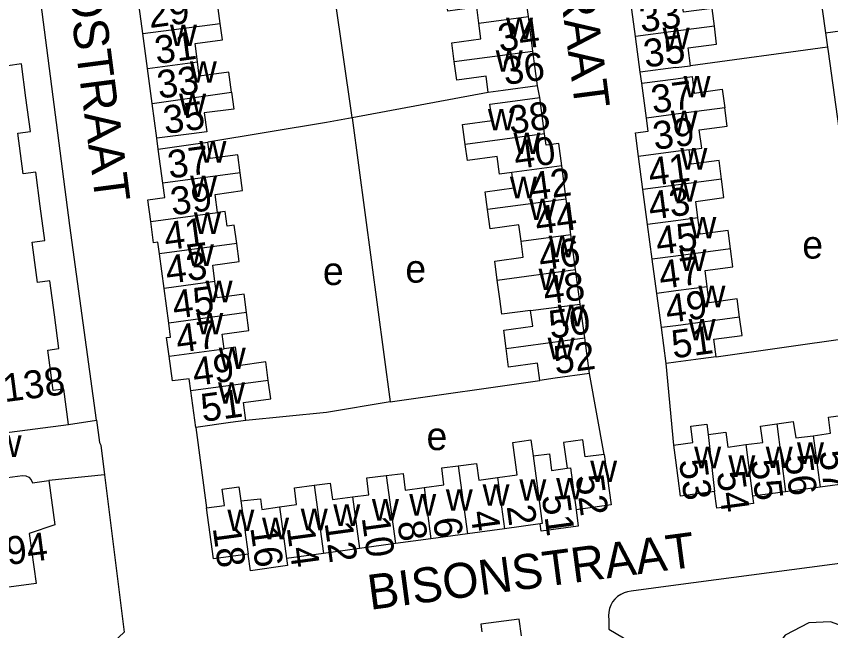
# Model space of a CAD drawing. Extents: x 162667 to 164645, y 379003 to 382150.
# Drawn here: x 163255.6 to 163372.2, y 381289.7 to 381377.6 of the extents above; entities that cross this region are included whole.
import ezdxf

# ---------------------------------------------------------------- set-up
doc = ezdxf.new("R2010")
doc.units = 0
for name, color, linetype in [('BLT_Basislijn', 7, 'Continuous'), ('BLT_Bebouwing', 7, 'Continuous'), ('BLT_Centroide', 7, 'Continuous'), ('BLT_Huisnummer', 7, 'Continuous'), ('BLT_Huisnummer_ tussenligend', 7, 'Continuous'), ('BLT_Huisnummer_reeks', 7, 'Continuous'), ('BLT_Onderverdeling_panden', 7, 'Continuous'), ('BLT_Straatnaam', 7, 'Continuous')]:
    doc.layers.add(name, color=color, linetype=linetype)

msp = doc.modelspace()

# ---------------------------------------------------------------- linework, layer by layer
at = {"layer": 'BLT_Basislijn'}
for p, q in [((163371.46, 381375.22), (163392.43, 381378.07)), ((163371.46, 381375.22), (163371.75, 381373.19)), ((163371.75, 381373.19), (163352.11, 381370.53)), ((163345.14, 381368.03), (163344.89, 381369.59)), ((163323.15, 381366.7), (163303.66, 381363.07)), ((163330.52, 381365.99), (163330.22, 381367.64)), ((163303.66, 381363.07), (163309.12, 381322.44)), ((163275.91, 381358.61), (163275.69, 381360.14)), ((163355.81, 381328.89), (163377.46, 381331.93)), ((163349.71, 381316.26), (163348.62, 381327.93)), ((163339.77, 381314.92), (163337.67, 381326.47)), ((163309.12, 381322.44), (163330.54, 381325.51)), ((163263.08, 381319.2), (163267.07, 381319.8)), ((163281.27, 381318.78), (163282.82, 381307.25)), ((163268.19, 381312), (163260.24, 381311.17)), ((163410.34, 381304.2), (163350, 381296.19)), ((163350, 381296.19), (163343.63, 381295.34))]:
    msp.add_line(p, q, dxfattribs=at)
for points in [[(163267.07, 381319.8), (163263.26, 381347.66), (163252.71, 381428.73)], [(163365.09, 381420.96), (163365.18, 381420.22), (163371.36, 381375.91), (163371.46, 381375.22)], [(163303.66, 381363.07), (163303.61, 381363.44), (163300, 381388.75), (163296.66, 381413.91)], [(163371.75, 381373.19), (163371.85, 381372.54), (163377.46, 381331.93)], [(163303.66, 381363.07), (163300, 381362.38), (163283.03, 381359.58)], [(163309.12, 381322.44), (163300, 381320.93), (163288.45, 381319.76)], [(163267.07, 381319.8), (163267.51, 381316.62), (163267.67, 381316.24), (163268.19, 381312)], [(163268.19, 381312), (163271.01, 381289.49), (163250.88, 381270.62), (163195.97, 381221.79)], [(163343.63, 381295.34), (163343.11, 381295.27), (163342.6, 381295.11), (163342.12, 381294.88), (163341.68, 381294.58), (163341.29, 381294.22), (163340.96, 381293.8), (163340.7, 381293.34), (163340.51, 381292.85), (163340.4, 381292.33), (163340.36, 381291.8), (163340.42, 381291.21)], [(163340.42, 381291.21), (163340.42, 381289.9), (163342.54, 381288.69), (163343.44, 381282.73), (163341.63, 381280.91), (163341.75, 381280.09)], [(163369.93, 381274.98), (163373.68, 381275.4), (163375.87, 381276.61), (163377.82, 381278.8), (163378.87, 381281.62), (163378.76, 381285.42), (163377.01, 381288.26), (163374.95, 381289.95), (163372.15, 381290.94), (163369.04, 381290.81), (163365.68, 381289.03), (163363.81, 381286.6), (163362.99, 381283.68), (163363.3, 381280.68), (163364.6, 381278.13), (163365.12, 381277.66)]]:
    msp.add_lwpolyline(points, dxfattribs=at)
at = {"layer": 'BLT_Bebouwing'}
for p, q in [((163328.9, 381377.57), (163328.25, 381382.52)), ((163273.71, 381375.12), (163273.05, 381380.11)), ((163344.23, 381374.7), (163343.59, 381379.61)), ((163329.56, 381372.63), (163328.9, 381377.57)), ((163274.37, 381370.13), (163273.71, 381375.12)), ((163344.89, 381369.59), (163344.23, 381374.7)), ((163330.22, 381367.64), (163329.56, 381372.63)), ((163275.03, 381365.14), (163274.37, 381370.13)), ((163350, 381370.25), (163344.89, 381369.59)), ((163350, 381370.25), (163352.11, 381370.53)), ((163345.14, 381368.03), (163350, 381368.67)), ((163345.81, 381363.02), (163345.14, 381368.03)), ((163331.22, 381360.78), (163330.52, 381365.99)), ((163275.69, 381360.14), (163275.03, 381365.14)), ((163276.58, 381353.72), (163275.91, 381358.61)), ((163345.31, 381352.82), (163344.69, 381357.52)), ((163334.32, 381351.45), (163333.68, 381356.2)), ((163345.98, 381347.81), (163345.31, 381352.82)), ((163334.99, 381346.4), (163334.32, 381351.45)), ((163346.64, 381342.86), (163345.98, 381347.81)), ((163335.67, 381341.37), (163334.99, 381346.4)), ((163276.74, 381338.66), (163276.07, 381343.61)), ((163347.29, 381337.95), (163346.64, 381342.86)), ((163336.33, 381336.43), (163335.67, 381341.37)), ((163277.41, 381333.71), (163276.74, 381338.66)), ((163347.94, 381333.05), (163347.29, 381337.95)), ((163336.99, 381331.57), (163336.33, 381336.43)), ((163348.62, 381327.93), (163347.94, 381333.05)), ((163337.67, 381326.47), (163336.99, 381331.57)), ((163350, 381328.11), (163348.62, 381327.93)), ((163281.27, 381318.78), (163280.57, 381324)), ((163253.53, 381317.94), (163263.08, 381319.2)), ((163349.71, 381316.26), (163350, 381316.3)), ((163350, 381314.11), (163349.71, 381316.26)), ((163375.61, 381310.9), (163370.66, 381310.24)), ((163365.72, 381309.58), (163361.01, 381308.96)), ((163370.66, 381310.24), (163365.72, 381309.58)), ((163330.58, 381304.97), (163325.48, 381304.28)), ((163325.48, 381304.28), (163320.2, 381303.56)), ((163314.95, 381302.85), (163309.86, 381302.16)), ((163320.2, 381303.56), (163314.95, 381302.85)), ((163309.86, 381302.16), (163304.71, 381301.46)), ((163299.56, 381300.76), (163294.29, 381300.04))]:
    msp.add_line(p, q, dxfattribs=at)
for points in [[(163284.79, 381376.58), (163284.41, 381379.42), (163280.48, 381378.9), (163280.19, 381381.05)], [(163321.81, 381376.62), (163321.51, 381378.9), (163317.36, 381378.35), (163317.01, 381381.02)], [(163355.53, 381376.17), (163355.2, 381378.72), (163351.09, 381378.19), (163350.78, 381380.55)], [(163281.52, 381371.07), (163281.17, 381373.71), (163285.1, 381374.23), (163284.79, 381376.58)], [(163318.29, 381371.14), (163317.94, 381373.8), (163322.11, 381374.36), (163321.81, 381376.62)], [(163352.11, 381370.53), (163351.78, 381373.08), (163355.86, 381373.62), (163355.53, 381376.17)], [(163256.97, 381365.95), (163256.33, 381370.78), (163254.39, 381370.52), (163254, 381373.42)], [(163286.4, 381366.73), (163286.01, 381369.61), (163281.78, 381369.05), (163281.52, 381371.07)], [(163323.15, 381366.7), (163322.84, 381369.03), (163318.65, 381368.47), (163318.29, 381371.14)], [(163350, 381368.67), (163352.34, 381368.98), (163352.65, 381366.62), (163356.67, 381367.16), (163357.02, 381364.51)], [(163286.4, 381366.73), (163286.72, 381364.33), (163282.49, 381363.78), (163282.85, 381361.08), (163280.65, 381360.79), (163275.69, 381360.14)], [(163330.22, 381367.64), (163325.27, 381366.98), (163323.15, 381366.7)], [(163256.19, 381357.98), (163255.81, 381360.88), (163257.61, 381361.12), (163256.97, 381365.95)], [(163319.87, 381359.25), (163319.49, 381362.11), (163323.7, 381362.68), (163323.38, 381365.03), (163325.56, 381365.33), (163330.52, 381365.99)], [(163351.93, 381358.49), (163353.72, 381358.73), (163353.37, 381361.33), (163357.37, 381361.86), (163357.02, 381364.51)], [(163344.69, 381357.52), (163344.24, 381360.9), (163346.06, 381361.14), (163345.81, 381363.02)], [(163333.68, 381356.2), (163333.25, 381359.39), (163331.44, 381359.14), (163331.22, 381360.78)], [(163275.91, 381358.61), (163280.93, 381359.3), (163283.03, 381359.58)], [(163287.62, 381355.22), (163287.28, 381357.78), (163283.35, 381357.25), (163283.03, 381359.58)], [(163326.55, 381355.24), (163324.78, 381355), (163324.44, 381357.53), (163320.18, 381356.96), (163319.87, 381359.25)], [(163356.56, 381354.31), (163356.2, 381356.97), (163352.2, 381356.44), (163351.93, 381358.49)], [(163259.01, 381350.41), (163258.36, 381355.31), (163256.58, 381355.07), (163256.19, 381357.98)], [(163284.39, 381349.53), (163284.04, 381352.11), (163287.97, 381352.65), (163287.62, 381355.22)], [(163323.07, 381349.94), (163322.71, 381352.48), (163326.84, 381353.04), (163326.55, 381355.24)], [(163353.18, 381348.76), (163352.86, 381351.11), (163356.91, 381351.65), (163356.56, 381354.31)], [(163274.83, 381348.23), (163274.4, 381351.35), (163276.85, 381351.68), (163276.58, 381353.72)], [(163258.24, 381342.38), (163257.86, 381345.27), (163259.66, 381345.51), (163259.01, 381350.41)], [(163287.14, 381345.11), (163286.78, 381347.73), (163285.78, 381347.59), (163285.49, 381349.66), (163284.39, 381349.53)], [(163327.87, 381345.44), (163327.56, 381347.75), (163323.43, 381347.2), (163323.07, 381349.94)], [(163276.07, 381343.61), (163275.84, 381345.28), (163275.24, 381345.2), (163274.83, 381348.23)], [(163357.84, 381344.35), (163357.49, 381346.95), (163353.49, 381346.42), (163353.18, 381348.76)], [(163284.02, 381339.64), (163283.7, 381341.98), (163287.49, 381342.5), (163287.14, 381345.11)], [(163324.45, 381339.86), (163324.08, 381342.58), (163328.18, 381343.13), (163327.87, 381345.44)], [(163354.5, 381338.91), (163354.2, 381341.21), (163358.19, 381341.74), (163357.84, 381344.35)], [(163261.04, 381334.89), (163260.4, 381339.73), (163258.62, 381339.49), (163258.24, 381342.38)], [(163329.22, 381335.48), (163325.11, 381334.96), (163324.81, 381337.15), (163324.45, 381339.86)], [(163288.55, 381335.22), (163288.19, 381337.83), (163284.33, 381337.3), (163284.02, 381339.64)], [(163359.14, 381334.53), (163358.79, 381337.15), (163354.81, 381336.62), (163354.5, 381338.91)], [(163285.35, 381330.02), (163285.07, 381332.1), (163288.9, 381332.62), (163288.55, 381335.22)], [(163325.73, 381330.05), (163325.37, 381332.7), (163329.52, 381333.25), (163329.22, 381335.48)], [(163260.46, 381326.95), (163260.08, 381329.84), (163261.68, 381330.05), (163261.04, 381334.89)], [(163355.81, 381328.89), (163355.48, 381331.39), (163359.49, 381331.92), (163359.14, 381334.53)], [(163277.45, 381328.95), (163277.08, 381331.63), (163277.68, 381331.71), (163277.41, 381333.71)], [(163291.66, 381325.51), (163291.3, 381328.14), (163287.35, 381327.6), (163286.99, 381330.24), (163285.35, 381330.02)], [(163330.54, 381325.51), (163330.21, 381327.97), (163326.08, 381327.41), (163325.73, 381330.05)], [(163280.57, 381324), (163280.33, 381325.75), (163277.93, 381325.43), (163277.45, 381328.95)], [(163355.81, 381328.89), (163353.58, 381328.59), (163350, 381328.11)], [(163263.08, 381319.2), (163262.41, 381324.27), (163260.84, 381324.06), (163260.46, 381326.95)], [(163337.67, 381326.47), (163332.72, 381325.8), (163330.54, 381325.51)], [(163288.45, 381319.76), (163288.1, 381322.34), (163292.01, 381322.87), (163291.66, 381325.51)], [(163369.68, 381317.59), (163372.14, 381317.95), (163371.86, 381320.25), (163374.37, 381320.56)], [(163288.45, 381319.76), (163286.23, 381319.46), (163281.27, 381318.78)], [(163350, 381316.3), (163352.46, 381316.63), (163352.18, 381318.94), (163354.47, 381319.22), (163354.63, 381317.78)], [(163360.03, 381316.31), (163362.49, 381316.64), (163362.16, 381318.94), (163364.5, 381319.28)], [(163364.5, 381319.28), (163366.83, 381319.62), (163367.18, 381317.29), (163369.68, 381317.59)], [(163354.63, 381317.78), (163357.18, 381318.11), (163357.47, 381315.97), (163360.03, 381316.31)], [(163324.49, 381311.6), (163327.3, 381311.98), (163326.67, 381316.63), (163329.27, 381317), (163329.58, 381314.69)], [(163339.77, 381314.92), (163337.03, 381314.55), (163336.69, 381317.01), (163333.95, 381316.64), (163334.45, 381312.93)], [(163329.58, 381314.69), (163331.92, 381314.98), (163332.21, 381312.63), (163334.45, 381312.93)], [(163339.77, 381314.92), (163340.75, 381307.68), (163335.73, 381307)], [(163313.96, 381310.19), (163316.8, 381310.57), (163316.49, 381312.97), (163318.85, 381313.28)], [(163318.85, 381313.28), (163321.49, 381313.62), (163321.8, 381311.24), (163324.49, 381311.6)], [(163355.57, 381309.61), (163350.68, 381308.96), (163350, 381314.11)], [(163254.34, 381311.62), (163256.45, 381311.91), (163256.96, 381311.86), (163257.37, 381311.66), (163257.73, 381311.29), (163257.9, 381310.85), (163260.24, 381311.17)], [(163303.71, 381308.83), (163306.04, 381309.14), (163305.76, 381311.55), (163308.54, 381311.88)], [(163308.54, 381311.88), (163310.98, 381312.16), (163311.25, 381309.82), (163313.96, 381310.19)], [(163260.24, 381311.17), (163261.09, 381304.86), (163257.42, 381303.61), (163258.44, 381296.46), (163250.91, 381295.46), (163237.24, 381290.3), (163225.06, 381282.2), (163214.98, 381271.54), (163207.58, 381258.92), (163196.15, 381222.43)], [(163298.24, 381310.5), (163300.54, 381310.8), (163300.85, 381308.44), (163303.71, 381308.83)], [(163282.82, 381307.25), (163285.4, 381307.6), (163285.06, 381309.94), (163287.46, 381310.29), (163287.74, 381308.27)], [(163293.29, 381307.4), (163295.72, 381307.73), (163295.41, 381310.13), (163298.24, 381310.5)], [(163361.01, 381308.96), (163361.15, 381307.91), (163355.89, 381307.21), (163355.57, 381309.61)], [(163287.74, 381308.27), (163290.54, 381308.58), (163290.75, 381307.05), (163293.29, 381307.4)], [(163288.77, 381300.63), (163283.81, 381299.96), (163282.82, 381307.25)], [(163335.73, 381307), (163336.04, 381304.65), (163330.72, 381303.93), (163330.58, 381304.97)], [(163304.71, 381301.46), (163299.56, 381300.76)], [(163294.29, 381300.04), (163294.43, 381299), (163289.1, 381298.28), (163288.77, 381300.63)], [(163327.9, 381288.96), (163327.57, 381291.36), (163322.1, 381290.61), (163322.24, 381289.54)]]:
    msp.add_lwpolyline(points, dxfattribs=at)
at = {"layer": 'BLT_Onderverdeling_panden'}
for p, q in [((163321.81, 381376.62), (163328.9, 381377.57)), ((163273.71, 381375.12), (163284.79, 381376.58)), ((163355.53, 381376.17), (163350, 381375.45)), ((163350, 381375.45), (163344.23, 381374.7)), ((163318.29, 381371.14), (163329.56, 381372.63)), ((163274.37, 381370.13), (163281.52, 381371.07)), ((163275.03, 381365.14), (163286.4, 381366.73)), ((163357.02, 381364.51), (163350, 381363.58)), ((163350, 381363.58), (163345.81, 381363.02)), ((163331.22, 381360.78), (163319.87, 381359.25)), ((163351.93, 381358.49), (163350, 381358.23)), ((163350, 381358.23), (163344.69, 381357.52)), ((163333.68, 381356.2), (163326.55, 381355.24)), ((163287.62, 381355.22), (163276.58, 381353.72)), ((163356.56, 381354.31), (163350, 381353.44)), ((163350, 381353.44), (163345.31, 381352.82)), ((163334.32, 381351.45), (163323.07, 381349.94)), ((163274.83, 381348.23), (163284.39, 381349.53)), ((163350, 381348.34), (163345.98, 381347.81)), ((163353.18, 381348.76), (163350, 381348.34)), ((163327.87, 381345.44), (163334.99, 381346.4)), ((163287.14, 381345.11), (163276.07, 381343.61)), ((163350, 381343.3), (163346.64, 381342.86)), ((163357.84, 381344.35), (163350, 381343.3)), ((163324.45, 381339.86), (163335.67, 381341.37)), ((163284.02, 381339.64), (163276.74, 381338.66)), ((163354.5, 381338.91), (163350, 381338.32)), ((163350, 381338.32), (163347.29, 381337.95)), ((163329.22, 381335.48), (163336.33, 381336.43)), ((163288.55, 381335.22), (163277.41, 381333.71)), ((163359.14, 381334.53), (163350, 381333.32)), ((163350, 381333.32), (163347.94, 381333.05)), ((163325.73, 381330.05), (163336.99, 381331.57)), ((163277.45, 381328.95), (163285.35, 381330.02)), ((163291.66, 381325.51), (163280.57, 381324)), ((163364.5, 381319.28), (163365.72, 381309.58)), ((163354.63, 381317.78), (163355.57, 381309.61)), ((163369.68, 381317.59), (163370.66, 381310.24)), ((163360.03, 381316.31), (163361.01, 381308.96)), ((163318.85, 381313.28), (163320.2, 381303.56)), ((163308.54, 381311.88), (163309.86, 381302.16)), ((163324.49, 381311.6), (163325.48, 381304.28)), ((163298.24, 381310.5), (163299.56, 381300.76)), ((163313.96, 381310.19), (163314.95, 381302.85)), ((163303.71, 381308.83), (163304.71, 381301.46)), ((163287.74, 381308.27), (163288.77, 381300.63)), ((163293.29, 381307.4), (163294.29, 381300.04))]:
    msp.add_line(p, q, dxfattribs=at)
for points in [[(163329.58, 381314.69), (163330.89, 381305.01), (163330.58, 381304.97)], [(163334.45, 381312.93), (163334.93, 381313), (163335.73, 381307)]]:
    msp.add_lwpolyline(points, dxfattribs=at)

# ---------------------------------------------------------------- texts
at = {"layer": 'BLT_Centroide'}
for s, p in [('w', (163325.7, 381374.34)), ('w', (163277.58, 381373.34)), ('w', (163348.13, 381372.88)), ('w', (163324.22, 381369.66)), ('w', (163280.43, 381368.09)), ('w', (163351.12, 381366)), ('w', (163278.89, 381363.44)), ('w', (163323.1, 381361.28)), ('w', (163349.28, 381361.03)), ('w', (163326.76, 381357.88)), ('w', (163281.8, 381356.66)), ('w', (163350.66, 381355.66)), ('w', (163280.47, 381351.72)), ('w', (163326.26, 381351.56)), ('w', (163349.21, 381351.06)), ('w', (163328.99, 381348.44)), ('w', (163281.01, 381346.47)), ('w', (163351.95, 381345.81)), ('w', (163331.81, 381343.12)), ('e', (163368.12, 381342.93)), ('w', (163280.01, 381341.88)), ('w', (163350.53, 381341.16)), ('e', (163299.48, 381339.15)), ('e', (163311.29, 381339.49)), ('w', (163330.35, 381338.44)), ('w', (163282.68, 381336.69)), ('w', (163353.25, 381335.97)), ('w', (163333.11, 381333.25)), ('w', (163281.35, 381332.09)), ('w', (163351.84, 381331.22)), ('w', (163331.66, 381328.53)), ('w', (163284.57, 381327.12)), ('w', (163284.47, 381322.16)), ('w', (163252.47, 381314.56)), ('e', (163314.32, 381315.53)), ('w', (163367.36, 381313.56)), ('w', (163352.64, 381312.94)), ('w', (163362.88, 381312.95)), ('w', (163357.53, 381311.7)), ('w', (163337.75, 381310.97)), ('w', (163322.34, 381307.58)), ('w', (163327.61, 381308.28)), ('w', (163332.88, 381308.47)), ('w', (163317.08, 381306.86)), ('w', (163306.5, 381305.44)), ('w', (163311.84, 381306.17)), ('w', (163296.31, 381304.06)), ('w', (163300.97, 381304.69)), ('w', (163285.8, 381303.94)), ('w', (163290.77, 381302.78))]:
    msp.add_text(s, height=4, dxfattribs=at).set_placement(p)
at = {"layer": 'BLT_Huisnummer'}
for s, rotation, p in [('29', 7.7015, (163274.69, 381375.9)), ('33', 7.5387, (163345.06, 381375.27)), ('34', 7.7348, (163324.81, 381372.48)), ('33', 7.7015, (163276.02, 381365.8)), ('37', 7.5387, (163346.74, 381363.69)), ('38', 7.7348, (163326.32, 381360.72)), ('37', 7.7015, (163277.52, 381354.36)), ('41', 7.5387, (163346.34, 381353.3)), ('42', 7.7348, (163329.37, 381351.21)), ('41', 7.7015, (163277, 381344.09)), ('45', 7.5387, (163347.41, 381343.44)), ('46', 7.7348, (163330.65, 381341.19)), ('45', 7.7015, (163278.2, 381334.3)), ('51', 7.5387, (163349.65, 381328.64)), ('52', 7.7348, (163332.79, 381326.38)), ('51', 7.7015, (163282.27, 381319.55)), ('57', 277.5626, (163370.52, 381315.32)), ('53', 277.5626, (163350.46, 381314.05)), ('56', 277.5626, (163365.54, 381314.7)), ('55', 277.5626, (163360.7, 381314.01)), ('52', 277.5796, (163335.65, 381311.83)), ('54', 277.5626, (163355.86, 381312.34)), ('51', 277.7368, (163330.81, 381308.96)), ('2', 277.7264, (163325.79, 381307.48)), ('10', 277.7264, (163305.03, 381305.87)), ('6', 277.7264, (163315.24, 381305.7)), ('18', 277.7264, (163283.7, 381304.4)), ('14', 277.7264, (163294.29, 381304.45))]:
    msp.add_text(s, height=4, rotation=rotation, dxfattribs=at).set_placement(p)
at = {"layer": 'BLT_Huisnummer_ tussenligend'}
for s, rotation, p in [('31', 7.7015, (163275.66, 381370.74)), ('35', 7.5387, (163345.65, 381370.25)), ('36', 7.7348, (163325.55, 381367.76)), ('35', 7.7015, (163276.89, 381360.75)), ('39', 7.5387, (163346.98, 381358.47)), ('40', 7.7348, (163327.1, 381355.72)), ('39', 7.7015, (163277.93, 381349.1)), ('43', 7.5387, (163346.36, 381348.48)), ('44', 7.7348, (163330.14, 381346.34)), ('43', 7.7015, (163277.21, 381339.3)), ('47', 7.5387, (163347.86, 381338.57)), ('48', 7.7348, (163331.31, 381336.33)), ('49', 7.5387, (163348.8, 381333.7)), ('50', 7.7348, (163332.09, 381331.46)), ('47', 7.7015, (163278.71, 381329.43)), ('49', 7.7015, (163281.08, 381324.69)), ('4', 277.7264, (163320.58, 381306.68)), ('12', 277.7264, (163299.71, 381305.12)), ('8', 277.7264, (163310.15, 381305.23)), ('16', 277.7264, (163289.08, 381304.45))]:
    msp.add_text(s, height=4, rotation=rotation, dxfattribs=at).set_placement(p)
at = {"layer": 'BLT_Huisnummer_reeks'}
for s, p in [('138', (163253.91, 381322.38)), ('68 t/m 194', (163235.21, 381296.54))]:
    msp.add_text(s, height=4, rotation=7.5442, dxfattribs=at).set_placement(p)
at = {"layer": 'BLT_Straatnaam'}
for s, rotation, p in [('POEMASTRAAT', 277.3951, (163329.14, 381414.26)), ('LUIPAARDSTRAAT', 277.4067, (163259.25, 381410.1)), ('BISONSTRAAT', 7.5623, (163306.23, 381292.66))]:
    msp.add_text(s, height=5, rotation=rotation, dxfattribs=at).set_placement(p)

doc.saveas('drawing.dxf')
